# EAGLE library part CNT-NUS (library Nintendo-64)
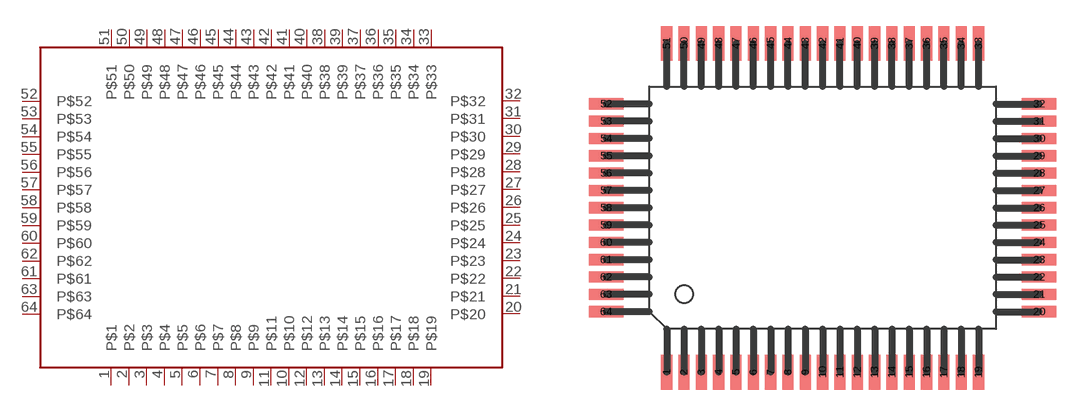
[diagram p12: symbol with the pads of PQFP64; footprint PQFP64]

Designator prefix -

## CNT-NUS  [PQFP64]
1  P$1
2  P$2
3  P$3
4  P$4
5  P$5
6  P$6
7  P$7
8  P$8
9  P$9
10  P$10
11  P$11
12  P$12
13  P$13
14  P$14
15  P$15
16  P$16
17  P$17
18  P$18
19  P$19
20  P$20
21  P$21
22  P$22
23  P$23
24  P$24
25  P$25
26  P$26
27  P$27
28  P$28
29  P$29
30  P$30
31  P$31
32  P$32
33  P$33
34  P$34
35  P$35
36  P$36
37  P$37
38  P$38
39  P$39
40  P$40
41  P$41
42  P$42
43  P$43
44  P$44
45  P$45
46  P$46
47  P$47
48  P$48
49  P$49
50  P$50
51  P$51
52  P$52
53  P$53
54  P$54
55  P$55
56  P$56
57  P$57
58  P$58
59  P$59
60  P$60
61  P$61
62  P$62
63  P$63
64  P$64

## Footprint PQFP64 (pad centres in mm)
smd 0.65 x 2: 1 -9,-9.5; 2 -8,-9.5; 3 -7,-9.5; 4 -6,-9.5; 5 -5,-9.5; 6 -4,-9.5; 7 -3,-9.5; 8 -2,-9.5; 9 -1,-9.5; 10 0,-9.5; 11 1,-9.5; 12 2,-9.5; 13 3,-9.5; 14 4,-9.5; 15 5,-9.5; 16 6,-9.5; 17 7,-9.5; 18 8,-9.5; 19 9,-9.5; 33 9,9.5; 34 8,9.5; 35 7,9.5; 36 6,9.5; 37 5,9.5; 38 4,9.5; 39 3,9.5; 40 2,9.5; 41 1,9.5; 42 0,9.5; 43 -1,9.5; 44 -2,9.5; 45 -3,9.5; 46 -4,9.5; 47 -5,9.5; 48 -6,9.5; 49 -7,9.5; 50 -8,9.5; 51 -9,9.5
smd 2 x 0.65: 20 12.5,-6; 21 12.5,-5; 22 12.5,-4; 23 12.5,-3; 24 12.5,-2; 25 12.5,-1; 26 12.5,0; 27 12.5,1; 28 12.5,2; 29 12.5,3; 30 12.5,4; 31 12.5,5; 32 12.5,6; 52 -12.5,6; 53 -12.5,5; 54 -12.5,4; 55 -12.5,3; 56 -12.5,2; 57 -12.5,1; 58 -12.5,0; 59 -12.5,-1; 60 -12.5,-2; 61 -12.5,-3; 62 -12.5,-4; 63 -12.5,-5; 64 -12.5,-6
